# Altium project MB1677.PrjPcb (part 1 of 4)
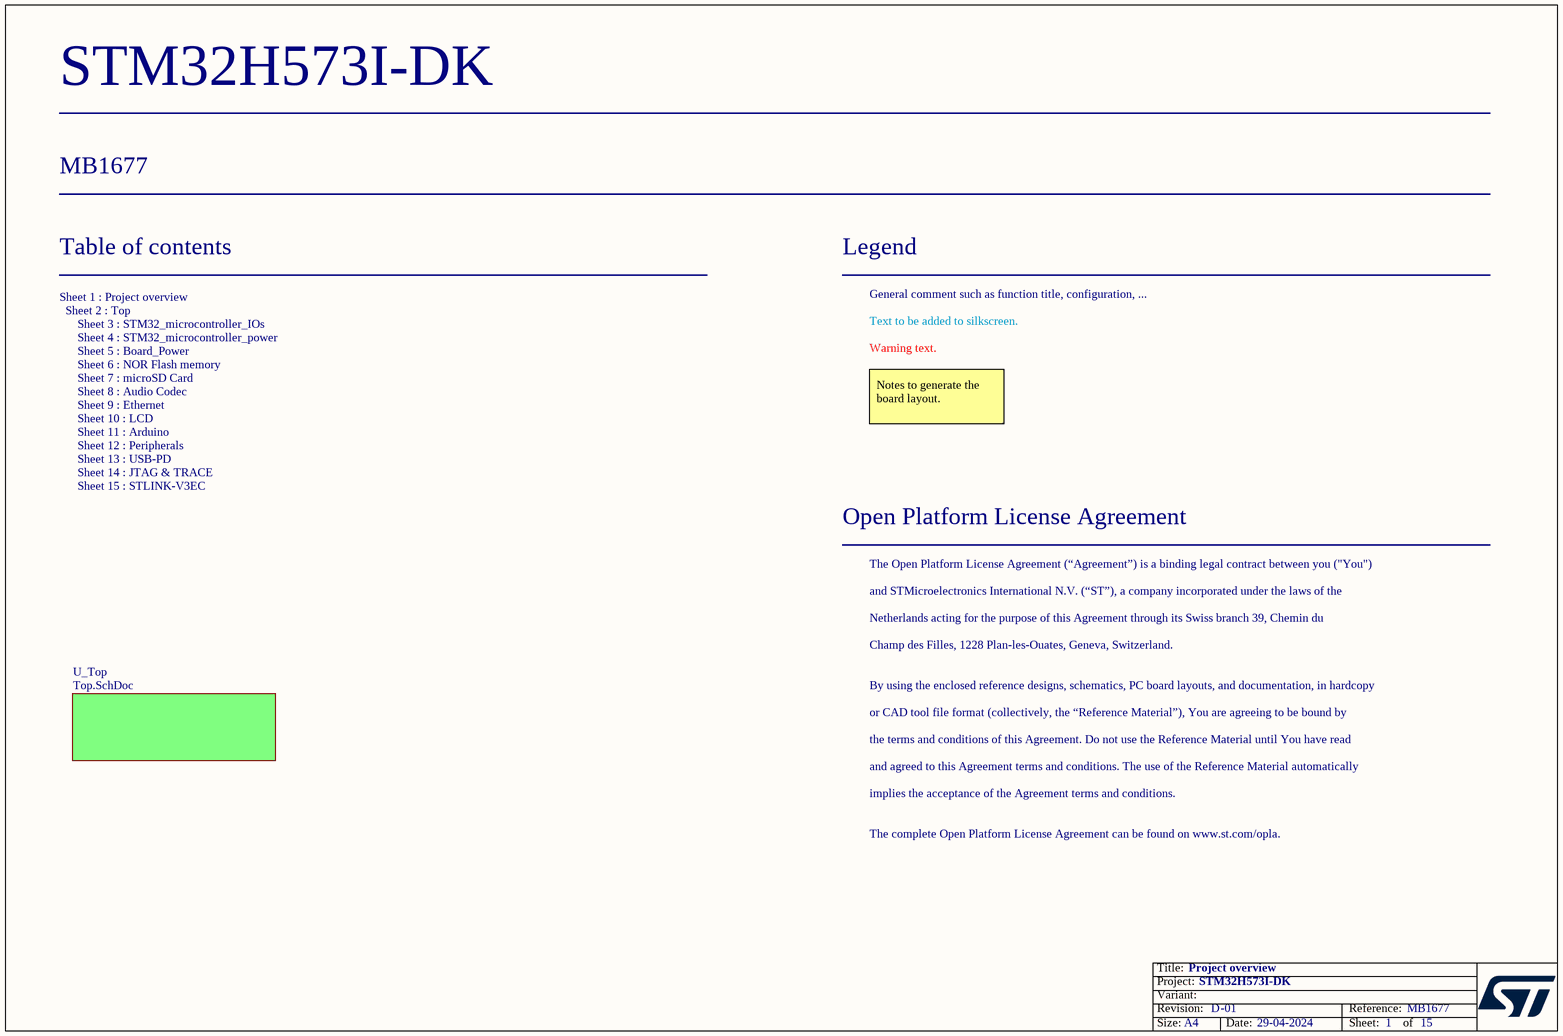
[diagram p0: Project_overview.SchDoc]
Board_Reference: MB1677; Board_PCB_Revision: D; Board_Name: STM32H573I-DK; Board_Document_Date: 29-04-2024; Board_Assembly_Revision: 01
15 sheets, 399 parts. Net scope: flat (ports and power ports of the same name join across sheets).
Board file: MB1677.PcbDoc
Sheets:
  Project_overview.SchDoc
    U_Top = Top.SchDoc
      U_Audio_Codec = Audio_Codec.SchDoc
      U_LCD = LCD.SchDoc
      U_Peripherals = Peripherals.SchDoc
      U_Arduino = Arduino.SchDoc
      U_JTAG = JTAG.SchDoc
      U_Ethernet = Ethernet.SchDoc
      U_STLINK_V3EC = STLINK_V3EC.SchDoc
      U_Board_power = Board_power.SchDoc
      U_STM32_microcontroller_power = STM32_microcontroller_power.SchDoc
      U_STM32_microcontroller_IOs = STM32_microcontroller_IOs.SchDoc
      U_USB-PD = USB-PD.SchDoc
      U_microSDcard = microSDcard.SchDoc
      U_NOR Flash memory = NOR_Flash_memory.SchDoc

## Sheet Project_overview.SchDoc: Project overview
size A4; Date: Not used; ApprovedBy: Not used; CheckedBy: Not used; Author: Not used; CompanyName: STMicroelectronics; DrawnBy: Not used; Engineer: Not used; Organization: Not used; Address1: Not used; Address2: Not used; Address3: Not used; Address4: Not used; DocumentNumber: 1; Revision: Not used; SheetNumber: 1; SheetTotal: 15

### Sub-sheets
U_Top = Top.SchDoc: no entries

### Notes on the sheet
- Table of contents
- Legend
- General comment such as function title, configuration, ...
- Text to be added to silkscreen.
- Warning text.
- Notes to generate the board layout.
- Sheet 1 : Project overview
  Sheet 2 : Top
  Sheet 3 : STM32_microcontroller_IOs
  Sheet 4 : STM32_microcontroller_power
  Sheet 5 : Board_Power
  Sheet 6 : NOR Flash memory
  Sheet 7 : microSD Card
  Sheet 8 : Audio Codec
  Sheet 9 : Ethernet
  Sheet 10 : LCD
  Sheet 11 : Arduino
  Sheet 12 : Peripherals
  Sheet 13 : USB-PD
  Sheet 14 : JTAG & TRACE
  Sheet 15 : STLINK-V3EC
- Open Platform License Agreement
- The Open Platform License Agreement (“Agreement”) is a binding legal contract between you ("You")
- and STMicroelectronics International N.V. (“ST”), a company incorporated under the laws of the
- Netherlands acting for the purpose of this Agreement through its Swiss branch 39, Chemin du
- Champ des Filles, 1228 Plan-les-Ouates, Geneva, Switzerland.
- By using the enclosed reference designs, schematics, PC board layouts, and documentation, in hardcopy
- or CAD tool file format (collectively, the “Reference Material”), You are agreeing to be bound by
- the terms and conditions of this Agreement. Do not use the Reference Material until You have read
- and agreed to this Agreement terms and conditions. The use of the Reference Material automatically
- implies the acceptance of the Agreement terms and conditions.
- The complete Open Platform License Agreement can be found on www.st.com/opla.

## Sheet Top.SchDoc: TOP
size A3; Date: Not used; ApprovedBy: Not used; CheckedBy: Not used; Author: Not used; CompanyName: STMicroelectronics; DrawnBy: Not used; Engineer: Not used; Organization: Not used; Address1: Not used; Address2: Not used; Address3: Not used; Address4: Not used; DocumentNumber: 2; Revision: Not used; SheetNumber: 2; SheetTotal: 15
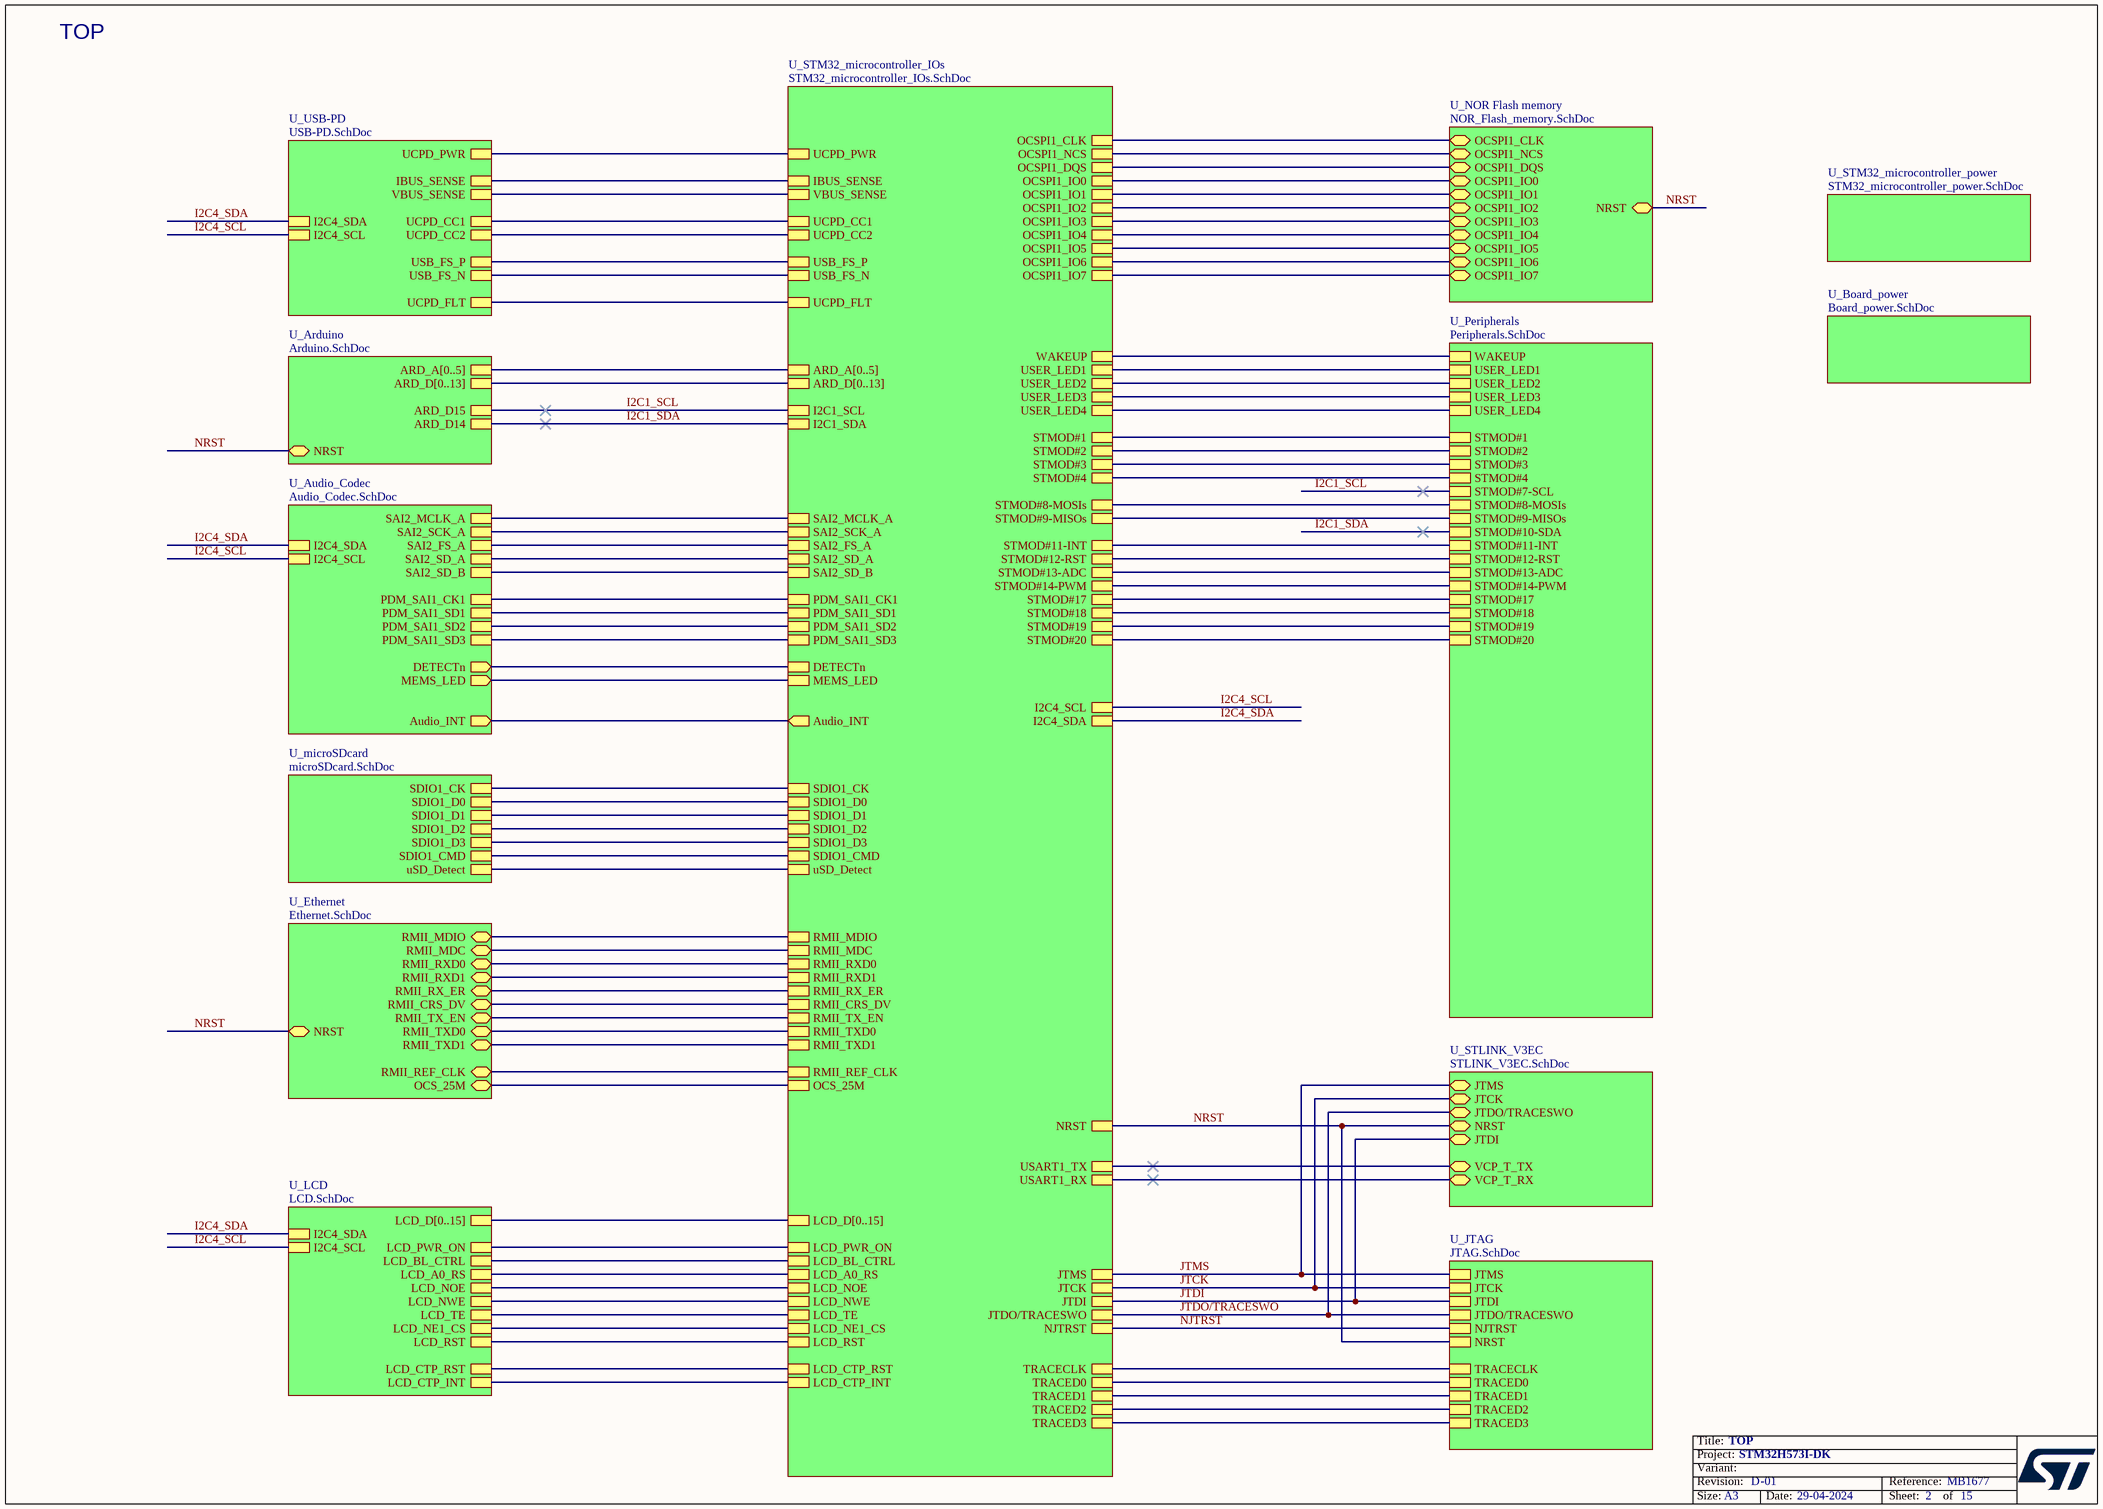
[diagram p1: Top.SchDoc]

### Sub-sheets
U_Arduino = Arduino.SchDoc: ARD_D15, ARD_D14, ARD_A[0..5], NRST (bidir), ARD_D[0..13]
U_Audio_Codec = Audio_Codec.SchDoc: Audio_INT (out), MEMS_LED (out), SAI2_SCK_A, SAI2_MCLK_A, SAI2_SD_B, DETECTn (out), SAI2_FS_A, SAI2_SD_A, I2C4_SCL, I2C4_SDA, PDM_SAI1_CK1, PDM_SAI1_SD2, PDM_SAI1_SD1, PDM_SAI1_SD3
U_Board_power = Board_power.SchDoc: no entries
U_Ethernet = Ethernet.SchDoc: RMII_TXD0 (bidir), RMII_TX_EN (bidir), RMII_RXD0 (bidir), RMII_REF_CLK (bidir), RMII_CRS_DV (bidir), RMII_MDC (bidir), RMII_MDIO (bidir), NRST (bidir), RMII_TXD1 (bidir), RMII_RXD1 (bidir), RMII_RX_ER (bidir), OCS_25M (bidir)
U_JTAG = JTAG.SchDoc: JTMS, JTCK, JTDI, JTDO/TRACESWO, NJTRST, NRST, TRACED0, TRACED1, TRACECLK, TRACED2, TRACED3
U_LCD = LCD.SchDoc: LCD_BL_CTRL, LCD_PWR_ON, LCD_RST, LCD_A0_RS, LCD_CTP_RST, LCD_TE, LCD_NOE, LCD_NE1_CS, LCD_D[0..15], LCD_CTP_INT, LCD_NWE, I2C4_SCL, I2C4_SDA
U_microSDcard = microSDcard.SchDoc: SDIO1_D0, SDIO1_D1, SDIO1_D2, SDIO1_D3, SDIO1_CMD, SDIO1_CK, uSD_Detect
U_NOR Flash memory = NOR_Flash_memory.SchDoc: NRST (bidir), OCSPI1_IO0 (bidir), OCSPI1_IO1 (bidir), OCSPI1_IO2 (bidir), OCSPI1_IO3 (bidir), OCSPI1_IO4 (bidir), OCSPI1_IO5 (bidir), OCSPI1_IO6 (bidir), OCSPI1_IO7 (bidir), OCSPI1_DQS (bidir), OCSPI1_CLK (bidir), OCSPI1_NCS (bidir)
U_Peripherals = Peripherals.SchDoc: WAKEUP, USER_LED2, USER_LED1, STMOD#2, STMOD#1, STMOD#4, USER_LED3, USER_LED4, STMOD#14-PWM, STMOD#8-MOSIs, STMOD#3, STMOD#13-ADC, STMOD#9-MISOs, STMOD#7-SCL, STMOD#10-SDA, STMOD#11-INT, STMOD#12-RST, STMOD#17, STMOD#18, STMOD#19, STMOD#20
U_STLINK_V3EC = STLINK_V3EC.SchDoc: JTCK (bidir), JTMS (bidir), JTDI (bidir), VCP_T_TX (bidir), VCP_T_RX (bidir), JTDO/TRACESWO (bidir), NRST (bidir)
U_STM32_microcontroller_IOs = STM32_microcontroller_IOs.SchDoc: OCSPI1_NCS, SAI2_MCLK_A, NRST, OCSPI1_DQS, OCSPI1_CLK, LCD_D[0..15], uSD_Detect, RMII_MDIO, SAI2_SD_B, SAI2_FS_A, SAI2_SCK_A, SAI2_SD_A, USER_LED2, JTMS, JTCK, JTDI, JTDO/TRACESWO, NJTRST, OCSPI1_IO1, OCSPI1_IO2, OCSPI1_IO3, OCSPI1_IO4, OCSPI1_IO7, OCSPI1_IO6, OCSPI1_IO5, RMII_CRS_DV, WAKEUP, USER_LED1, RMII_RXD1, UCPD_CC1, STMOD#1, STMOD#2, STMOD#4, STMOD#3, STMOD#9-MISOs, STMOD#8-MOSIs, STMOD#13-ADC, USART1_TX, USART1_RX, STMOD#11-INT, STMOD#12-RST, STMOD#14-PWM, STMOD#18, RMII_REF_CLK, RMII_RXD0, RMII_TXD0, ARD_A[0..5], ARD_D[0..13], RMII_MDC, RMII_TXD1, RMII_TX_EN, SDIO1_D0, SDIO1_D1, SDIO1_D2, SDIO1_D3, SDIO1_CK, SDIO1_CMD, OCSPI1_IO0, LCD_RST, LCD_BL_CTRL, LCD_CTP_RST, LCD_PWR_ON, USER_LED3, USER_LED4, UCPD_CC2, OCS_25M, LCD_CTP_INT, LCD_NE1_CS, LCD_NOE, LCD_NWE, USB_FS_N, USB_FS_P, RMII_RX_ER, LCD_A0_RS, I2C4_SCL, I2C4_SDA, IBUS_SENSE, UCPD_PWR, UCPD_FLT, VBUS_SENSE, DETECTn, MEMS_LED, LCD_TE, I2C1_SCL, I2C1_SDA, Audio_INT (out), PDM_SAI1_SD3, PDM_SAI1_CK1, PDM_SAI1_SD2, PDM_SAI1_SD1, STMOD#19, STMOD#20, STMOD#17, TRACECLK, TRACED0, TRACED1, TRACED2, TRACED3
U_STM32_microcontroller_power = STM32_microcontroller_power.SchDoc: no entries
U_USB-PD = USB-PD.SchDoc: UCPD_PWR, IBUS_SENSE, UCPD_CC1, UCPD_CC2, UCPD_FLT, USB_FS_P, USB_FS_N, VBUS_SENSE, I2C4_SCL, I2C4_SDA

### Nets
I2C1_SCL: sheet U_Peripherals/STMOD#7-SCL, sheet U_Arduino/ARD_D15, sheet U_STM32_microcontroller_IOs/I2C1_SCL
I2C1_SDA: sheet U_Peripherals/STMOD#10-SDA, sheet U_Arduino/ARD_D14, sheet U_STM32_microcontroller_IOs/I2C1_SDA
I2C4_SCL: sheet U_Audio_Codec/I2C4_SCL, sheet U_LCD/I2C4_SCL, sheet U_STM32_microcontroller_IOs/I2C4_SCL, sheet U_USB-PD/I2C4_SCL
I2C4_SDA: sheet U_Audio_Codec/I2C4_SDA, sheet U_LCD/I2C4_SDA, sheet U_STM32_microcontroller_IOs/I2C4_SDA, sheet U_USB-PD/I2C4_SDA
JTCK: sheet U_JTAG/JTCK, sheet U_STLINK_V3EC/JTCK, sheet U_STM32_microcontroller_IOs/JTCK
JTDI: sheet U_JTAG/JTDI, sheet U_STLINK_V3EC/JTDI, sheet U_STM32_microcontroller_IOs/JTDI
JTDO/TRACESWO: sheet U_JTAG/JTDO/TRACESWO, sheet U_STLINK_V3EC/JTDO/TRACESWO, sheet U_STM32_microcontroller_IOs/JTDO/TRACESWO
JTMS: sheet U_JTAG/JTMS, sheet U_STLINK_V3EC/JTMS, sheet U_STM32_microcontroller_IOs/JTMS
NJTRST: sheet U_JTAG/NJTRST, sheet U_STM32_microcontroller_IOs/NJTRST
NRST: sheet U_Arduino/NRST, sheet U_JTAG/NRST, sheet U_Ethernet/NRST, sheet U_STLINK_V3EC/NRST, sheet U_STM32_microcontroller_IOs/NRST, sheet U_NOR Flash memory/NRST
(unnamed): sheet U_Audio_Codec/Audio_INT, sheet U_STM32_microcontroller_IOs/Audio_INT
(unnamed): sheet U_Audio_Codec/MEMS_LED, sheet U_STM32_microcontroller_IOs/MEMS_LED  [a separate net that carries the same name]
(unnamed): sheet U_Audio_Codec/SAI2_SCK_A, sheet U_STM32_microcontroller_IOs/SAI2_SCK_A  [a separate net that carries the same name]
(unnamed): sheet U_Audio_Codec/SAI2_MCLK_A, sheet U_STM32_microcontroller_IOs/SAI2_MCLK_A  [a separate net that carries the same name]
(unnamed): sheet U_Audio_Codec/SAI2_SD_B, sheet U_STM32_microcontroller_IOs/SAI2_SD_B  [a separate net that carries the same name]
(unnamed): sheet U_Audio_Codec/DETECTn, sheet U_STM32_microcontroller_IOs/DETECTn  [a separate net that carries the same name]
(unnamed): sheet U_Audio_Codec/SAI2_FS_A, sheet U_STM32_microcontroller_IOs/SAI2_FS_A  [a separate net that carries the same name]
(unnamed): sheet U_Audio_Codec/SAI2_SD_A, sheet U_STM32_microcontroller_IOs/SAI2_SD_A  [a separate net that carries the same name]
(unnamed): sheet U_Audio_Codec/PDM_SAI1_CK1, sheet U_STM32_microcontroller_IOs/PDM_SAI1_CK1  [a separate net that carries the same name]
(unnamed): sheet U_Audio_Codec/PDM_SAI1_SD2, sheet U_STM32_microcontroller_IOs/PDM_SAI1_SD2  [a separate net that carries the same name]
(unnamed): sheet U_Audio_Codec/PDM_SAI1_SD1, sheet U_STM32_microcontroller_IOs/PDM_SAI1_SD1  [a separate net that carries the same name]
(unnamed): sheet U_Audio_Codec/PDM_SAI1_SD3, sheet U_STM32_microcontroller_IOs/PDM_SAI1_SD3  [a separate net that carries the same name]
(unnamed): sheet U_LCD/LCD_BL_CTRL, sheet U_STM32_microcontroller_IOs/LCD_BL_CTRL  [a separate net that carries the same name]
(unnamed): sheet U_LCD/LCD_PWR_ON, sheet U_STM32_microcontroller_IOs/LCD_PWR_ON  [a separate net that carries the same name]
(unnamed): sheet U_LCD/LCD_RST, sheet U_STM32_microcontroller_IOs/LCD_RST  [a separate net that carries the same name]
(unnamed): sheet U_LCD/LCD_A0_RS, sheet U_STM32_microcontroller_IOs/LCD_A0_RS  [a separate net that carries the same name]
(unnamed): sheet U_LCD/LCD_CTP_RST, sheet U_STM32_microcontroller_IOs/LCD_CTP_RST  [a separate net that carries the same name]
(unnamed): sheet U_LCD/LCD_TE, sheet U_STM32_microcontroller_IOs/LCD_TE  [a separate net that carries the same name]
(unnamed): sheet U_LCD/LCD_NOE, sheet U_STM32_microcontroller_IOs/LCD_NOE  [a separate net that carries the same name]
(unnamed): sheet U_LCD/LCD_NE1_CS, sheet U_STM32_microcontroller_IOs/LCD_NE1_CS  [a separate net that carries the same name]
(unnamed): sheet U_LCD/LCD_CTP_INT, sheet U_STM32_microcontroller_IOs/LCD_CTP_INT  [a separate net that carries the same name]
(unnamed): sheet U_LCD/LCD_NWE, sheet U_STM32_microcontroller_IOs/LCD_NWE  [a separate net that carries the same name]
(unnamed): sheet U_Peripherals/WAKEUP, sheet U_STM32_microcontroller_IOs/WAKEUP  [a separate net that carries the same name]
(unnamed): sheet U_Peripherals/USER_LED2, sheet U_STM32_microcontroller_IOs/USER_LED2  [a separate net that carries the same name]
(unnamed): sheet U_Peripherals/USER_LED1, sheet U_STM32_microcontroller_IOs/USER_LED1  [a separate net that carries the same name]
(unnamed): sheet U_Peripherals/STMOD#2, sheet U_STM32_microcontroller_IOs/STMOD#2  [a separate net that carries the same name]
(unnamed): sheet U_Peripherals/STMOD#1, sheet U_STM32_microcontroller_IOs/STMOD#1  [a separate net that carries the same name]
(unnamed): sheet U_Peripherals/STMOD#4, sheet U_STM32_microcontroller_IOs/STMOD#4  [a separate net that carries the same name]
(unnamed): sheet U_Peripherals/USER_LED3, sheet U_STM32_microcontroller_IOs/USER_LED3  [a separate net that carries the same name]
(unnamed): sheet U_Peripherals/USER_LED4, sheet U_STM32_microcontroller_IOs/USER_LED4  [a separate net that carries the same name]
(unnamed): sheet U_Peripherals/STMOD#14-PWM, sheet U_STM32_microcontroller_IOs/STMOD#14-PWM  [a separate net that carries the same name]
(unnamed): sheet U_Peripherals/STMOD#8-MOSIs, sheet U_STM32_microcontroller_IOs/STMOD#8-MOSIs  [a separate net that carries the same name]
(unnamed): sheet U_Peripherals/STMOD#3, sheet U_STM32_microcontroller_IOs/STMOD#3  [a separate net that carries the same name]
(unnamed): sheet U_Peripherals/STMOD#13-ADC, sheet U_STM32_microcontroller_IOs/STMOD#13-ADC  [a separate net that carries the same name]
(unnamed): sheet U_Peripherals/STMOD#9-MISOs, sheet U_STM32_microcontroller_IOs/STMOD#9-MISOs  [a separate net that carries the same name]
(unnamed): sheet U_Peripherals/STMOD#11-INT, sheet U_STM32_microcontroller_IOs/STMOD#11-INT  [a separate net that carries the same name]
(unnamed): sheet U_Peripherals/STMOD#12-RST, sheet U_STM32_microcontroller_IOs/STMOD#12-RST  [a separate net that carries the same name]
(unnamed): sheet U_Peripherals/STMOD#17, sheet U_STM32_microcontroller_IOs/STMOD#17  [a separate net that carries the same name]
(unnamed): sheet U_Peripherals/STMOD#18, sheet U_STM32_microcontroller_IOs/STMOD#18  [a separate net that carries the same name]
(unnamed): sheet U_Peripherals/STMOD#19, sheet U_STM32_microcontroller_IOs/STMOD#19  [a separate net that carries the same name]
(unnamed): sheet U_Peripherals/STMOD#20, sheet U_STM32_microcontroller_IOs/STMOD#20  [a separate net that carries the same name]
(unnamed): sheet U_JTAG/TRACED0, sheet U_STM32_microcontroller_IOs/TRACED0  [a separate net that carries the same name]
(unnamed): sheet U_JTAG/TRACED1, sheet U_STM32_microcontroller_IOs/TRACED1  [a separate net that carries the same name]
(unnamed): sheet U_JTAG/TRACECLK, sheet U_STM32_microcontroller_IOs/TRACECLK  [a separate net that carries the same name]
(unnamed): sheet U_JTAG/TRACED2, sheet U_STM32_microcontroller_IOs/TRACED2  [a separate net that carries the same name]
(unnamed): sheet U_JTAG/TRACED3, sheet U_STM32_microcontroller_IOs/TRACED3  [a separate net that carries the same name]
(unnamed): sheet U_Ethernet/RMII_TXD0, sheet U_STM32_microcontroller_IOs/RMII_TXD0  [a separate net that carries the same name]
(unnamed): sheet U_Ethernet/RMII_TX_EN, sheet U_STM32_microcontroller_IOs/RMII_TX_EN  [a separate net that carries the same name]
(unnamed): sheet U_Ethernet/RMII_RXD0, sheet U_STM32_microcontroller_IOs/RMII_RXD0  [a separate net that carries the same name]
(unnamed): sheet U_Ethernet/RMII_REF_CLK, sheet U_STM32_microcontroller_IOs/RMII_REF_CLK  [a separate net that carries the same name]
(unnamed): sheet U_Ethernet/RMII_CRS_DV, sheet U_STM32_microcontroller_IOs/RMII_CRS_DV  [a separate net that carries the same name]
(unnamed): sheet U_Ethernet/RMII_MDC, sheet U_STM32_microcontroller_IOs/RMII_MDC  [a separate net that carries the same name]
(unnamed): sheet U_Ethernet/RMII_MDIO, sheet U_STM32_microcontroller_IOs/RMII_MDIO  [a separate net that carries the same name]
(unnamed): sheet U_Ethernet/RMII_TXD1, sheet U_STM32_microcontroller_IOs/RMII_TXD1  [a separate net that carries the same name]
(unnamed): sheet U_Ethernet/RMII_RXD1, sheet U_STM32_microcontroller_IOs/RMII_RXD1  [a separate net that carries the same name]
(unnamed): sheet U_Ethernet/RMII_RX_ER, sheet U_STM32_microcontroller_IOs/RMII_RX_ER  [a separate net that carries the same name]
(unnamed): sheet U_Ethernet/OCS_25M, sheet U_STM32_microcontroller_IOs/OCS_25M  [a separate net that carries the same name]
(unnamed): sheet U_STLINK_V3EC/VCP_T_TX, sheet U_STM32_microcontroller_IOs/USART1_TX  [a separate net that carries the same name]
(unnamed): sheet U_STLINK_V3EC/VCP_T_RX, sheet U_STM32_microcontroller_IOs/USART1_RX  [a separate net that carries the same name]
(unnamed): sheet U_STM32_microcontroller_IOs/OCSPI1_NCS, sheet U_NOR Flash memory/OCSPI1_NCS  [a separate net that carries the same name]
(unnamed): sheet U_STM32_microcontroller_IOs/OCSPI1_DQS, sheet U_NOR Flash memory/OCSPI1_DQS  [a separate net that carries the same name]
(unnamed): sheet U_STM32_microcontroller_IOs/OCSPI1_CLK, sheet U_NOR Flash memory/OCSPI1_CLK  [a separate net that carries the same name]
(unnamed): sheet U_STM32_microcontroller_IOs/uSD_Detect, sheet U_microSDcard/uSD_Detect  [a separate net that carries the same name]
(unnamed): sheet U_STM32_microcontroller_IOs/OCSPI1_IO1, sheet U_NOR Flash memory/OCSPI1_IO1  [a separate net that carries the same name]
(unnamed): sheet U_STM32_microcontroller_IOs/OCSPI1_IO2, sheet U_NOR Flash memory/OCSPI1_IO2  [a separate net that carries the same name]
(unnamed): sheet U_STM32_microcontroller_IOs/OCSPI1_IO3, sheet U_NOR Flash memory/OCSPI1_IO3  [a separate net that carries the same name]
(unnamed): sheet U_STM32_microcontroller_IOs/OCSPI1_IO4, sheet U_NOR Flash memory/OCSPI1_IO4  [a separate net that carries the same name]
(unnamed): sheet U_STM32_microcontroller_IOs/OCSPI1_IO7, sheet U_NOR Flash memory/OCSPI1_IO7  [a separate net that carries the same name]
(unnamed): sheet U_STM32_microcontroller_IOs/OCSPI1_IO6, sheet U_NOR Flash memory/OCSPI1_IO6  [a separate net that carries the same name]
(unnamed): sheet U_STM32_microcontroller_IOs/OCSPI1_IO5, sheet U_NOR Flash memory/OCSPI1_IO5  [a separate net that carries the same name]
(unnamed): sheet U_STM32_microcontroller_IOs/UCPD_CC1, sheet U_USB-PD/UCPD_CC1  [a separate net that carries the same name]
(unnamed): sheet U_STM32_microcontroller_IOs/SDIO1_D0, sheet U_microSDcard/SDIO1_D0  [a separate net that carries the same name]
(unnamed): sheet U_STM32_microcontroller_IOs/SDIO1_D1, sheet U_microSDcard/SDIO1_D1  [a separate net that carries the same name]
(unnamed): sheet U_STM32_microcontroller_IOs/SDIO1_D2, sheet U_microSDcard/SDIO1_D2  [a separate net that carries the same name]
(unnamed): sheet U_STM32_microcontroller_IOs/SDIO1_D3, sheet U_microSDcard/SDIO1_D3  [a separate net that carries the same name]
(unnamed): sheet U_STM32_microcontroller_IOs/SDIO1_CK, sheet U_microSDcard/SDIO1_CK  [a separate net that carries the same name]
(unnamed): sheet U_STM32_microcontroller_IOs/SDIO1_CMD, sheet U_microSDcard/SDIO1_CMD  [a separate net that carries the same name]
(unnamed): sheet U_STM32_microcontroller_IOs/OCSPI1_IO0, sheet U_NOR Flash memory/OCSPI1_IO0  [a separate net that carries the same name]
(unnamed): sheet U_STM32_microcontroller_IOs/UCPD_CC2, sheet U_USB-PD/UCPD_CC2  [a separate net that carries the same name]
(unnamed): sheet U_STM32_microcontroller_IOs/USB_FS_N, sheet U_USB-PD/USB_FS_N  [a separate net that carries the same name]
(unnamed): sheet U_STM32_microcontroller_IOs/USB_FS_P, sheet U_USB-PD/USB_FS_P  [a separate net that carries the same name]
(unnamed): sheet U_STM32_microcontroller_IOs/IBUS_SENSE, sheet U_USB-PD/IBUS_SENSE  [a separate net that carries the same name]
(unnamed): sheet U_STM32_microcontroller_IOs/UCPD_PWR, sheet U_USB-PD/UCPD_PWR  [a separate net that carries the same name]
(unnamed): sheet U_STM32_microcontroller_IOs/UCPD_FLT, sheet U_USB-PD/UCPD_FLT  [a separate net that carries the same name]
(unnamed): sheet U_STM32_microcontroller_IOs/VBUS_SENSE, sheet U_USB-PD/VBUS_SENSE  [a separate net that carries the same name]

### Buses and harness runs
bus sheet U_Arduino/ARD_A[0..5] = sheet U_STM32_microcontroller_IOs/ARD_A[0..5]
bus sheet U_Arduino/ARD_D[0..13] = sheet U_STM32_microcontroller_IOs/ARD_D[0..13]
bus sheet U_LCD/LCD_D[0..15] = sheet U_STM32_microcontroller_IOs/LCD_D[0..15]

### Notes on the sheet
- TOP

## Sheet Audio_Codec.SchDoc: Audio Codec
size A4; Date: Not used; ApprovedBy: Not used; CheckedBy: Not used; Author: Not used; CompanyName: STMicroelectronics; DrawnBy: Not used; Engineer: Not used; Organization: Not used; Address1: Not used; Address2: Not used; Address3: Not used; Address4: Not used; DocumentNumber: 8; Revision: Not used; SheetNumber: 8; SheetTotal: 15
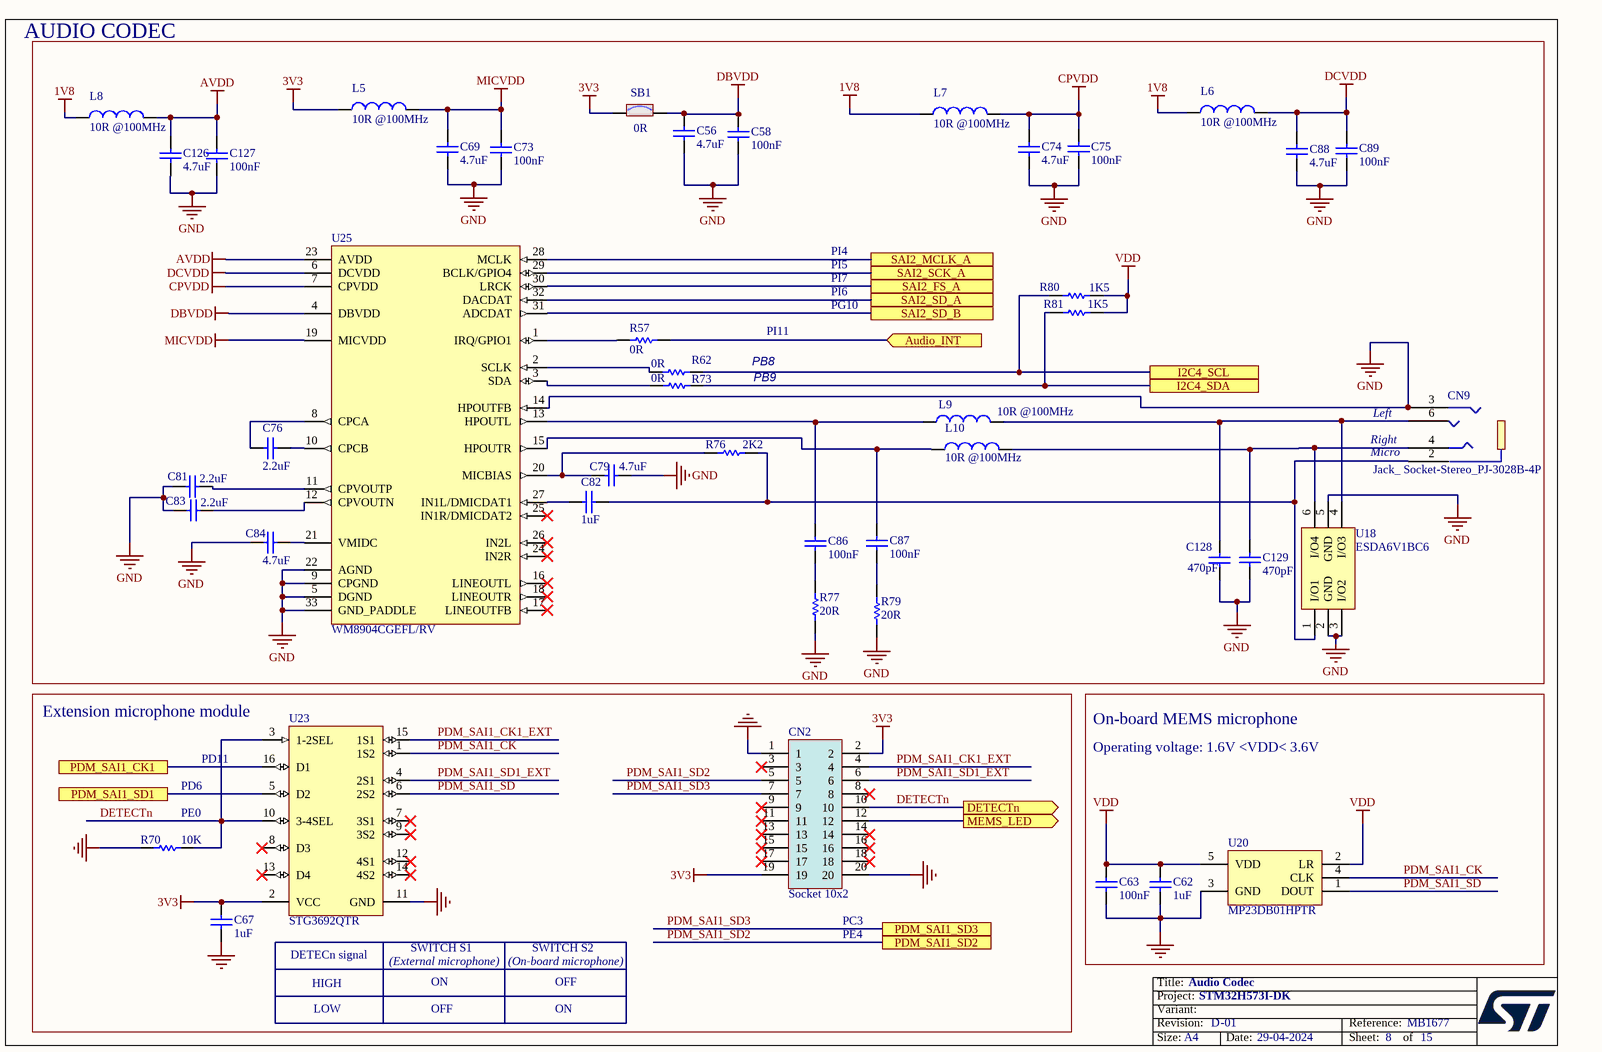
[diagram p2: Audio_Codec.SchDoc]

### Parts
C56  value 4.7uF  [C0603]  (hidden comment: Capacitor)
C58  value 100nF  [C0402]  (hidden comment: Capacitor)
C62  value 1uF  [C0402]  (hidden comment: Capacitor)
C63  value 100nF  [C0402]  (hidden comment: Capacitor)
C67  value 1uF  [C0402]  (hidden comment: Capacitor)
C69  value 4.7uF  [C0603]  (hidden comment: Capacitor)
C73  value 100nF  [C0402]  (hidden comment: Capacitor)
C74  value 4.7uF  [C0603]  (hidden comment: Capacitor)
C75  value 100nF  [C0402]  (hidden comment: MCD-00006)
C76  value 2.2uF  [C0603]  (hidden comment: Capacitor)
C79  value 4.7uF  [C0603]  (hidden comment: Capacitor)
C81  value 2.2uF  [C0603]  (hidden comment: Capacitor)
C82  value 1uF  [C0603]  (hidden comment: Capacitor)
C83  value 2.2uF  [C0603]  (hidden comment: Capacitor)
C84  value 4.7uF  [C0603]  (hidden comment: Capacitor)
C86  value 100nF  [C0402]  (hidden comment: Capacitor)
C87  value 100nF  [C0402]  (hidden comment: Capacitor)
C88  value 4.7uF  [C0603]  (hidden comment: Capacitor)
C89  value 100nF  [C0402]  (hidden comment: Capacitor)
C126  value 4.7uF  [C0603]  (hidden comment: Capacitor)
C127  value 100nF  [C0402]  (hidden comment: Capacitor)
C128  value 470pF  [C0402]  (hidden comment: Capacitor)
C129  value 470pF  [C0402]  (hidden comment: Capacitor)
CN2  Socket 10x2  [CON_FCI_20021311-XXX20XXLF]
CN9  value Jack_ Socket-Stereo_PJ-3028B-4P  [CON_PHONE-JACK-3P5_HY_PJ3028B]  (hidden comment: Jack_PJ3028B-3_4P)
L5  value 10R @100MHz  [IND_0402_MURATA_BLM15H_H0P5]  (hidden comment: Inductor)
L6  value 10R @100MHz  [IND_0402_MURATA_BLM15H_H0P5]  (hidden comment: Inductor)
L7  value 10R @100MHz  [IND_0402_MURATA_BLM15H_H0P5]  (hidden comment: Inductor)
L8  value 10R @100MHz  [IND_0402_MURATA_BLM15H_H0P5]  (hidden comment: Inductor)
L9  value 10R @100MHz  [IND_0402_MURATA_BLM15H_H0P5]  (hidden comment: Inductor)
L10  value 10R @100MHz  [IND_0402_MURATA_BLM15H_H0P5]  (hidden comment: Inductor)
R57  value 0R  [R0603]  (hidden comment: Resistor)
R62  value 0R  [R0603]  (hidden comment: Resistor)
R70  value 10K  [R0402]  (hidden comment: Resistor)
R73  value 0R  [R0603]  (hidden comment: Resistor)
R76  value 2K2  [R0402]  (hidden comment: Resistor)
R77  value 20R  [R0603]  (hidden comment: Resistor)
R79  value 20R  [R0603]  (hidden comment: Resistor)
R80  value 1K5  [R0402]  (hidden comment: Resistor)
R81  value 1K5  [R0402]  (hidden comment: Resistor)
SB1  value 0R  [SOLDER-BRIDGE_R0603-0R]  (hidden comment: SB_ON)
U18  ESDA6V1BC6  [ESD_SOT23-6L]
U20  value MP23DB01HPTR  [MIC_STM_MP23DB01MMTR]  (hidden comment: MP23DB01MMTR)
U23  STG3692QTR  [ICC_UFQFN16-EPAD_2P6X1P8_P040]
U25  WM8904CGEFL/RV  [ICC_QFN32-EPAD_4X4_P040]

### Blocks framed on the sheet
Extension microphone module: C67 CN2 R70 U23
On-board MEMS microphone: C62 C63 U20

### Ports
Audio_INT (in), DETECTn (out), I2C4_SCL, I2C4_SDA, MEMS_LED (out), PDM_SAI1_CK1, PDM_SAI1_SD1, PDM_SAI1_SD2, PDM_SAI1_SD3, SAI2_FS_A, SAI2_MCLK_A, SAI2_SCK_A, SAI2_SD_A, SAI2_SD_B

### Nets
1V8: L6.1 L7.1 L8.1
3V3: C67.2 CN2.2 CN2.19 L5.1 SB1.1 U23.2(VCC)
AVDD: C126.2 C127.2 L8.2 U25.23(AVDD)
CPVDD: C74.2 C75.2 L7.2 U25.7(CPVDD)
DBVDD: C56.2 C58.2 SB1.2 U25.4(DBVDD)
DCVDD: C88.2 C89.2 L6.2 U25.6(DCVDD)
GND: C56.1 C58.1 C62.2 C63.1 C67.1 C69.1 C73.1 C74.1 C75.1 C79.2 C81.1 C83.1 C84.1 C88.1 C89.1 C126.1 C127.1 C128.1 C129.1 CN2.1 CN2.20 CN9.3 R70.1 R77.1 R79.1 U18.2(GND) U18.3(I/O2) U18.5(GND) U20.3(GND) U23.11(GND) U25.5(DGND) U25.9(CPGND) U25.14(HPOUTFB) U25.22(AGND) U25.33(GND_PADDLE)
MICVDD: C69.2 C73.2 L5.2 U25.19(MICVDD)
VDD: C62.1 C63.2 R80.2 R81.2 U20.2(LR) U20.5(VDD)
Audio_INT: R57.1 ; port Audio_INT
DETECTn: CN2.10 R70.2 U23.3(1-2SEL) U23.10(3-4SEL) ; port DETECTn
I2C4_SCL: R62.2 R80.1 ; port I2C4_SCL
I2C4_SDA: R73.2 R81.1 ; port I2C4_SDA
MEMS_LED: CN2.12 ; port MEMS_LED
PDM_SAI1_CK: U20.4(CLK) U23.1(1S2)
PDM_SAI1_CK1: U23.16(D1) ; port PDM_SAI1_CK1
PDM_SAI1_CK1_EXT: CN2.4 U23.15(1S1)
PDM_SAI1_SD: U20.1(DOUT) U23.6(2S2)
PDM_SAI1_SD1: U23.5(D2) ; port PDM_SAI1_SD1
PDM_SAI1_SD1_EXT: CN2.6 U23.4(2S1)
PDM_SAI1_SD2: CN2.5 ; port PDM_SAI1_SD2
PDM_SAI1_SD3: CN2.7 ; port PDM_SAI1_SD3
SAI2_FS_A: U25.30(LRCK) ; port SAI2_FS_A
SAI2_MCLK_A: U25.28(MCLK) ; port SAI2_MCLK_A
SAI2_SCK_A: U25.29(BCLK/GPIO4) ; port SAI2_SCK_A
SAI2_SD_A: U25.32(DACDAT) ; port SAI2_SD_A
SAI2_SD_B: U25.31(ADCDAT) ; port SAI2_SD_B
NetC76_1: C76.1 U25.8(CPCA)
NetC76_2: C76.2 U25.10(CPCB)
NetC79_1: C79.1 R76.1 U25.20(MICBIAS)
NetC81_2: C81.2 U25.11(CPVOUTP)
NetC82_1: C82.1 U25.27(IN1L/DMICDAT1)
NetC82_2: C82.2 CN9.2 R76.2 U18.1(I/O1)
NetC83_2: C83.2 U25.12(CPVOUTN)
NetC84_2: C84.2 U25.21(VMIDC)
NetC86_1: C86.1 R77.2
NetC86_2: C86.2 L9.1 U25.13(HPOUTL)
NetC87_1: C87.1 R79.2
NetC87_2: C87.2 L10.1 U25.15(HPOUTR)
NetC128_2: C128.2 CN9.6 L9.2 U18.4(I/O3)
NetC129_2: C129.2 CN9.4 L10.2 U18.6(I/O4)
NetR57_2: R57.2 U25.1(IRQ/GPIO1)
NetR62_1: R62.1 U25.2(SCLK)
NetR73_1: R73.1 U25.3(SDA)

Not connected (* = marked no-connect by the designer): CN2 3* 8* 9* 11* 13* 14* 15* 16* 17* 18*; U23 7(3S1)* 8(D3)* 9(3S2)* 12(4S1)* 13(D4)* 14(4S2)*; U25 16(LINEOUTL)* 17(LINEOUTFB)* 18(LINEOUTR)* 24(IN2R)* 25(IN1R/DMICDAT2)* 26(IN2L)*

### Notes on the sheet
- AUDIO CODEC
- PI4
- PI5
- PI7
- PI6
- PG10
- PB8
- PB9
- PI11
- (near CN9) Right
- Micro
- (near CN9) Left
- PD6
- PD11
- Operating voltage: 1.6V <VDD< 3.6V
- (near R70) PE0
- PE4
- (near CN2) PC3
- DETECn signal
- HIGH
- (External microphone)
- (near U23) SWITCH S1
- ON
- (On-board microphone)
- SWITCH S2
- OFF
- LOW

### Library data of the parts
C56 C69 C74 C79 C84 C88 C126 = MCD-00009: Capacitor, MLCC, 4.7uF, 16V, X5R, +/-10%, 0603, T=0.8mm; Part_Preference: Recommended; Manufacturer: YAGEO; Manufacturer_Part_Number: CC0603KRX5R7BB475; Partial_Alternate_Internal_Part_Number: MCD-03565; Component_Country_Of_Origin: China; Alternate_EMS: A; ShowFields: YES; ID: 2471
C58 C73 C75 C86 C87 C89 C127 = MCD-00006: Capacitor, MLCC, 100nF, 16V, X7R, +/-10%, 0402, T=0.5mm; Part_Preference: Recommended; Manufacturer: YAGEO; Manufacturer_Part_Number: CC0402KRX7R7BB104; Partial_Alternate_Internal_Part_Number: MCD-03299; Order_Code_RS: 9402047; Component_Country_Of_Origin: China; ShowFields: YES; ID: 2474
C62 = MCD-01722: Capacitor, 1uF, 10V, X5R, 10%, 0402, T=0.5mm; Manufacturer_Part_Number: CC0402KRX5R6BB105; Manufacturer: YAGEO; Part_Preference: Recommended; Provided_By: SUBCO; Component_Country_Of_Origin: China; ID: 3822; ShowFields: YES
C63 = MCD-00006: Capacitor, MLCC, 100nF, 16V, X7R, +/-10%, 0402, T=0.5mm; Part_Preference: Recommended; Manufacturer: YAGEO; Manufacturer_Part_Number: CC0402KRX7R7BB104; Partial_Alternate_Internal_Part_Number: MCD-03299; Order_Code_RS: 9402047; Component_Country_Of_Origin: China; ID: 2474; ShowFields: YES
C67 = MCD-00095: Capacitor, MLCC, 1uF, 25V, X5R, +/-10%, 0402, T=0.5mm; Part_Preference: Recommended; Manufacturer: MURATA; Manufacturer_Part_Number: GRM155R61E105KA12; Order_Code_RS: 2218855; Component_Country_Of_Origin: Japan°°; ID: 2772; ShowFields: YES
C76 C81 C83 = MCD-00012: Capacitor, MLCC, 2.2uF, 10V, X5R, +/- 10%, 0603, T=0.8mm; BMS_Part_Number: 9142010; Part_Preference: Recommended; Manufacturer: YAGEO; Manufacturer_Part_Number: CC0603KRX5R6BB225; Partial_Alternate_Internal_Part_Number: MCD-00551; Order_Code_RS: 2370679; Component_Country_Of_Origin: China; ShowFields: YES; ID: 2467
C82 = MCD-00010: Capacitor, MLCC, 1uF, 16V, X5R, +/-10%, 0603, T=0.8mm; Part_Preference: Recommended; Manufacturer: YAGEO; Manufacturer_Part_Number: CC0603KRX5R7BB105; Order_Code_RS: 2370680; Component_Country_Of_Origin: China; ShowFields: YES; ID: 2470
C128 C129 = MCD-00724: Capacitor, MLCC, 470pF, 50V, NPO, +/-5%, 0402, T=0.5mm; Part_Preference: Recommended; Manufacturer: YAGEO; Manufacturer_Part_Number: CC0402JRNPO9BN471; Order_Code_RS: 199-2186; Component_Country_Of_Origin: China; ShowFields: YES; ID: 3023
CN2 = MCD-00147: Socket for MB1299, 10x2, 1.27mm, VR, TH, Height 4.30mm/2.40mm; Part_Preference: Recommended; Part_Type: Connector; Manufacturer: AMPHENOL ICC; Manufacturer_Part_Number: 20021311-00020T4LF; Alternate_Manufacturer: JIUBABA; Alternate_Manufacturer_Part_Number: 234220S1410; Partial_Alternate_Internal_Part_Number: MCD-03007; Component_Country_Of_Origin: China; ID: 2719; Order_Code_RS: 170-8859; ShowFields: YES
CN9 = MCD-00263: Connector Jack Socket Stereo 3.5mm, 4 pins, RA, SMT, Black; Part_Preference: Recommended; Manufacturer: QIAOD; Manufacturer_Part_Number: PJ-3028B-4P; Component_Country_Of_Origin: Unknown; ID: 2608; ShowFields: YES
L5-L10 = MCD-02381: Ferrite bead, 10R @100MHz, 5R, 0.75A, 0.07R, 0402, T=0.22mm; Part_Preference: Recommended; Manufacturer: MURATA; Manufacturer_Part_Number: BLM02AX100SN1D; Component_Country_Of_Origin: Japan°°; ShowFields: YES; ID: 4487
R57 R62 R73 = MCD-00056: Resistor, 0R, 0603, +/-5%, 1/10W; Part_Preference: Recommended; Manufacturer: YAGEO; Manufacturer_Part_Number: RC0603JR-070RL; Order_Code_RS: 9233130RL; Component_Country_Of_Origin: China; ShowFields: YES; ID: 2536
R70 = MCD-00053: Resistor,10K,0402,1%,1/16W; BMS_Part_Number: 9131590; Part_Preference: Recommended; Manufacturer: YAGEO; Manufacturer_Part_Number: RC0402FR-0710KL; Order_Code_RS: 9239359; Component_Country_Of_Origin: China; ID: 2539; ShowFields: YES
R76 = MCD-00057: Resistor, 2K2, 0402, +/-1%, 1/16W; Part_Preference: Recommended; Manufacturer: YAGEO; Manufacturer_Part_Number: RC0402FR-072K2L; Order_Code_RS: 9239278; Component_Country_Of_Origin: China; ShowFields: YES; ID: 2534
R77 R79 = MCD-00345: Resistor, 20R, 0603, +/-1%, 1/10W; Part_Preference: Recommended; Manufacturer: YAGEO; Manufacturer_Part_Number: RC0603FR-0720RL; Component_Country_Of_Origin: China; ShowFields: YES; ID: 2933
R80 R81 = MCD-00068: Resistor, 1K5, 0402, +/-1%, 1/16W; Manufacturer_Part_Number: RC0402FR-071K5L; Manufacturer: YAGEO; Part_Preference: Recommended; Order_Code_RS: 9239251; Component_Country_Of_Origin: China; ShowFields: YES; ID: 2524
SB1 = MCD-00071: Resistor, 0R, SB0603, 5%, 0.1W; Manufacturer_Part_Number: RC0603JR-070RL; Manufacturer: YAGEO; Manufacturer_HQ_COO: Unknown; Part_Preference: Recommended; Component_Country_Of_Origin: China; ID: 2521; Order_Code_RS: 199-5647; ShowFields: YES
U18 = MCD-00247: Quad Bidir ESD protection; BMS_Part_Number: 9179038; Part_Preference: Recommended; Part_Type: Diode; Manufacturer: STMICROELECTRONICS; Manufacturer_HQ_COO: EU; Component_Country_Of_Origin: China; ID: 2624; Order_Code_RS: 248-805; ShowFields: YES
U20 = MCD-02122: MEMS sensors , omnidirectionnal digital microphone; Part_Type: IC; Part_Preference: Recommended; Manufacturer: STMICROELECTRONICS; Manufacturer_HQ_COO: EU; Component_Country_Of_Origin: China; ShowFields: YES; ID: 4222
U23 = MCD-00317: Low voltage high bandwidth quad SPDT switch; BMS_Part_Number: 9159018; Part_Preference: Recommended; Part_Type: IC; Manufacturer: STMICROELECTRONICS; Manufacturer_HQ_COO: EU; Component_Country_Of_Origin: Thailand; ID: 2961; ShowFields: YES
U25 = MCD-03825: Audio Codec, Ultra Low-Power Codec for Portable Audio Applications; Part_Type: IC; Part_Preference: Recommended; Manufacturer: CIRRUS LOGIC; Component_Country_Of_Origin: Taiwan; ShowFields: YES; ID: 5941

## Sheet LCD.SchDoc: LCD
size A4; Date: Not used; ApprovedBy: Not used; CheckedBy: Not used; Author: Not used; CompanyName: STMicroelectronics; DrawnBy: Not used; Engineer: Not used; Organization: Not used; Address1: Not used; Address2: Not used; Address3: Not used; Address4: Not used; DocumentNumber: 10; Revision: Not used; SheetNumber: 10; SheetTotal: 15
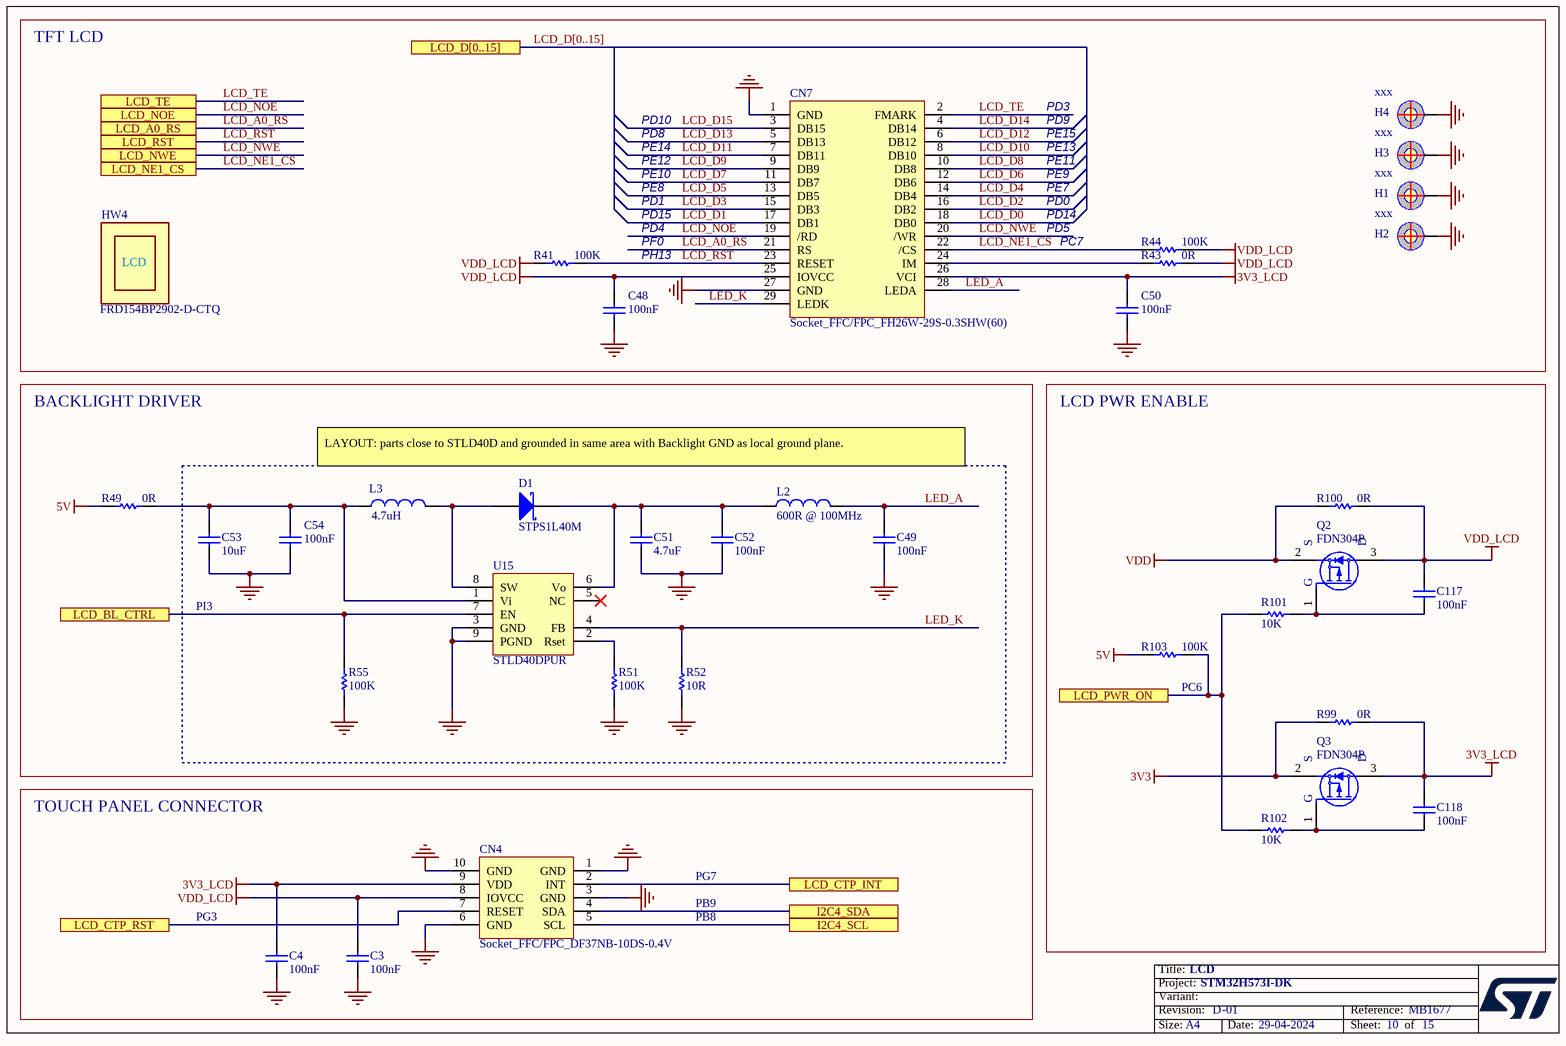
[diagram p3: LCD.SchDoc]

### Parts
C3  value 100nF  [C0402]  (hidden comment: Capacitor)
C4  value 100nF  [C0402]  (hidden comment: Capacitor)
C48  value 100nF  [C0402]  (hidden comment: Capacitor)
C49  value 100nF  [C0603]  (hidden comment: Capacitor)
C50  value 100nF  [C0402]  (hidden comment: Capacitor)
C51  value 4.7uF  [C1206_H1P25]  (hidden comment: Capacitor)
C52  value 100nF  [C0603]  (hidden comment: Capacitor)
C53  value 10uF  [C0603]  (hidden comment: Capacitor)
C54  value 100nF  [C0402]  (hidden comment: Capacitor)
C117  value 100nF  [C0402]  (hidden comment: Capacitor)
C118  value 100nF  [C0402]  (hidden comment: Capacitor)
CN4  value Socket_FFC/FPC_DF37NB-10DS-0.4V  [CON_HRS_DF37NB-10DS-04V]  (hidden comment: DF37NB-10DS-0.4V)
CN7  value Socket_FFC/FPC_FH26W-29S-0.3SHW(60)  [CON_HRS_FH26-29S-03SHW]  (hidden comment: FH26-29S-0.3SHW)
D1  STPS1L40M  [DIO_DO216-AA]
H1  value xxx  [PTH_M1261-3005-N_3P5X6_M3_H14]  (hidden comment: POSITION HOLE)  (no BOM)
H2  value xxx  [PTH_M1261-3005-N_3P5X6_M3_H14]  (hidden comment: POSITION HOLE)  (no BOM)
H3  value xxx  [PTH_M1261-3005-N_3P5X6_M3_H14]  (hidden comment: POSITION HOLE)  (no BOM)
H4  value xxx  [PTH_M1261-3005-N_3P5X6_M3_H14]  (hidden comment: POSITION HOLE)  (no BOM)
HW4  value FRD154BP2902-D-CTQ  [LCD_DRAWING_FRIDA_FRD154BP2902-D-CTQ]  (hidden comment: LCD_MODULE)  (mechanical)
L2  value 600R @ 100MHz  [L0603]  (hidden comment: BEAD)
L3  value 4.7uH  [L1210_LQH]  (hidden comment: Inductor)
Q2  value FDN304P  [MOS_SOT23]  (hidden comment: MOSFET_FDN304P)
Q3  value FDN304P  [MOS_SOT23]  (hidden comment: MOSFET_FDN304P)
R41  value 100K  [R0402]  (hidden comment: Resistor)
R43  value 0R  [R0402]  (hidden comment: Resistor)
R44  value 100K  [R0402]  (hidden comment: Resistor)
R49  value 0R  [R0402]  (hidden comment: Resistor)
R51  value 100K  [R0402]  (hidden comment: Resistor)
R52  value 10R  [R0402]  (hidden comment: Resistor)
R55  value 100K  [R0402]  (hidden comment: Resistor)
R99  value 0R  [R0402]  (hidden comment: Resistor)
R100  value 0R  [R0402]  (hidden comment: Resistor)
R101  value 10K  [R0402]  (hidden comment: Resistor)
R102  value 10K  [R0402]  (hidden comment: Resistor)
R103  value 100K  [R0402]  (hidden comment: Resistor)
U15  STLD40DPUR  [ICC_QFN8-EPAD_3X3_P065]

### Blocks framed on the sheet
TFT LCD: C48 C50 CN7 H1-H4 HW4 R41 R43 R44
BACKLIGHT DRIVER: R49
LCD PWR ENABLE: C117 C118 Q2 Q3 R99-R103
PI3: C49 C51-C54 D1 L2 L3 R51 R52 R55 U15
TOUCH PANEL CONNECTOR: C3 C4 CN4

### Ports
I2C4_SCL, I2C4_SDA, LCD_A0_RS, LCD_BL_CTRL, LCD_CTP_INT, LCD_CTP_RST, LCD_D[0..15], LCD_NE1_CS, LCD_NOE, LCD_NWE, LCD_PWR_ON, LCD_RST, LCD_TE

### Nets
3V3: Q3.2(S) R99.1
3V3_LCD: C4.2 C50.1 C118.2 CN4.9(VDD) CN7.26(VCI) Q3.3(D) R99.2
5V: R49.1 R103.1
GND: C3.1 C4.1 C48.2 C49.1 C50.2 C51.1 C52.1 C53.1 C54.2 CN4.1(GND) CN4.3(GND) CN4.6(GND) CN4.10(GND) CN7.1(GND) CN7.27(GND) H1.1 H2.1 H3.1 H4.1 R51.1 R52.1 R55.1 U15.3(GND) U15.9(PGND)
VDD: Q2.2(S) R100.1
VDD_LCD: C3.2 C48.1 C117.2 CN4.8(IOVCC) CN7.25(IOVCC) Q2.3(D) R41.1 R43.2 R44.2 R100.2
I2C4_SCL: CN4.5(SCL) ; port I2C4_SCL
I2C4_SDA: CN4.4(SDA) ; port I2C4_SDA
LCD_A0_RS: CN7.21(RS) ; port LCD_A0_RS
LCD_BL_CTRL: R55.2 U15.7(EN) ; port LCD_BL_CTRL
LCD_CTP_INT: CN4.2(INT) ; port LCD_CTP_INT
LCD_CTP_RST: CN4.7(RESET) ; port LCD_CTP_RST
LCD_D0: CN7.18(DB0)
LCD_D1: CN7.17(DB1)
LCD_D2: CN7.16(DB2)
LCD_D3: CN7.15(DB3)
LCD_D4: CN7.14(DB4)
LCD_D5: CN7.13(DB5)
LCD_D6: CN7.12(DB6)
LCD_D7: CN7.11(DB7)
LCD_D8: CN7.10(DB8)
LCD_D9: CN7.9(DB9)
LCD_D10: CN7.8(DB10)
LCD_D11: CN7.7(DB11)
LCD_D12: CN7.6(DB12)
LCD_D13: CN7.5(DB13)
LCD_D14: CN7.4(DB14)
LCD_D15: CN7.3(DB15)
LCD_NE1_CS: CN7.22(/CS) R44.1 ; port LCD_NE1_CS
LCD_NOE: CN7.19(/RD) ; port LCD_NOE
LCD_NWE: CN7.20(/WR) ; port LCD_NWE
LCD_PWR_ON: R101.1 R102.1 R103.2 ; port LCD_PWR_ON
LCD_RST: CN7.23(RESET) R41.2 ; port LCD_RST
LCD_TE: CN7.2(FMARK) ; port LCD_TE
LED_A: C49.2 CN7.28(LEDA) L2.2
LED_K: CN7.29(LEDK) R52.2 U15.4(FB)
NetC51_2: C51.2 C52.2 D1.2(K) L2.1 U15.6(Vo)
NetC53_2: C53.2 C54.1 L3.1 R49.2 U15.1(Vi)
NetC117_1: C117.1 Q2.1(G) R101.2
NetC118_1: C118.1 Q3.1(G) R102.2
NetCN7_24: CN7.24(IM) R43.1
NetD1_1: D1.1(A) L3.2 U15.8(SW)
NetR51_2: R51.2 U15.2(Rset)

Not connected (* = marked no-connect by the designer): U15 5(NC)*

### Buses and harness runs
bus LCD_D[0..15] = port LCD_D[0..15]

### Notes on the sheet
- PD3
- PD10
- PD8
- PE14
- PE12
- PE10
- PD9
- PE15
- PE13
- PE11
- PE9
- PE8
- PD1
- PD15
- PD4
- PF0
- PE7
- PD0
- PD14
- PD5
- PC7
- PH13
- LAYOUT: parts close to STLD40D and grounded in same area with Backlight GND as local ground plane.
- (near R103) PC6
- PG3
- PB9
- PB8
- PG7

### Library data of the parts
C3 C4 C48 C50 C54 C117 C118 = MCD-00006: Capacitor, MLCC, 100nF, 16V, X7R, +/-10%, 0402, T=0.5mm; Manufacturer_Part_Number: CC0402KRX7R7BB104; Manufacturer: YAGEO; Part_Preference: Recommended; Partial_Alternate_Internal_Part_Number: MCD-03299; Component_Country_Of_Origin: China; ID: 2474; Order_Code_RS: 9402047; ShowFields: YES
C49 C52 = MCD-01099: Capacitor,100nF,50V,X7R,10%,0603; Manufacturer_Part_Number: CC0603KRX7R9BB104; Manufacturer: YAGEO; BMS_Part_Number: 9142278; Part_Preference: Recommended; Provided_By: SUBCO; Component_Country_Of_Origin: China; ID: 3397; Order_Code_RS: 669-8767; ShowFields: YES
C51 = MCD-00013: Capacitor, MLCC, 4.7uF, 50V, X7R, 10%, 1206, T=1,27mm; Manufacturer_Part_Number: 12065C475KAT2A; Manufacturer: AVX; Part_Preference: Recommended; ECCN_US: EAR99; ECCN_EU: NEC; Provided_By: SUBCO; Component_Country_Of_Origin: China, Malaysia; ID: 2466; Order_Code_RS: 1908177; ShowFields: YES
C53 = MCD-00099: Capacitor, MLCC, 10uF, 10V, X5R, +/-10%, 0603, T=0.8mm; Manufacturer_Part_Number: GRM188R61A106KE69D; Manufacturer: MURATA; Part_Preference: Recommended; Partial_Alternate_Internal_Part_Number: MCD-03152; Component_Country_Of_Origin: Japan°°; ID: 2770; Order_Code_RS: 2494233; ShowFields: YES
CN4 = MCD-00021: Socket FCC/FPC, 5x2, 0.4mm, VR, SMT, 0.98mm, Frida touch panel; Part_Type: Connector; Manufacturer_Part_Number: DF37NB-10DS-0.4V (5x); Manufacturer: HIROSE; Part_Preference: Recommended; Provided_By: SUBCO; Component_Country_Of_Origin: Japan; ID: 2499; ShowFields: YES
CN7 = MCD-01798: Socket FCC/FPC, 29pins, 0.6mm, SMT, for FRIDA LCD (replacement of obsolete component MCD-00020 FH26-29S-0.3SHW); Part_Type: Connector; Manufacturer_Part_Number: FH26W-29S-0.3SHW(60); Manufacturer: HIROSE; Part_Preference: Recommended; Provided_By: SUBCO; Component_Country_Of_Origin: Japan; ID: 3898; ShowFields: YES
D1 = MCD-00033: Low Drop power Schottky rectifier(1A, 40V, 0.4V); Part_Type: Diode; Manufacturer: STMICROELECTRONICS; BMS_Part_Number: 9151085; Manufacturer_HQ_COO: EU; Part_Preference: Recommended; ECCN_US: EAR99; ECCN_EU: NEC; Provided_By: SUBCO with ST control; Component_Country_Of_Origin: China; ID: 2485; Order_Code_RS: 189-4505; ShowFields: YES
H1-H4 = MCD-00035: POSITION HOLE C6D3R5; Part_Type: Misc; Part_Preference: Recommended; Component_Country_Of_Origin: Unknown; ID: 2482; ShowFields: YES
HW4 = MCD-01797: TFT LCD 1.54inch 240RGB x 240 pixels + CTP; BMS_Part_Number: 8001061; Part_Type: Display; Part_Preference: Recommended; Manufacturer: SHENZEN FRIDA LCD; Component_Country_Of_Origin: China; ID: 3897; ShowFields: YES
L2 = MCD-00047: SMD Chip ferrite bead, 600R@100MHz +/-25%, 350mA, 500mohm DC, 0603, T=0.8mm; Part_Type: Inductor; Manufacturer_Part_Number: FCM1608KF-601T03; Manufacturer: TAI-TECH; Part_Preference: Recommended; Partial_Alternate_Internal_Part_Number: MCD-02959; Provided_By: SUBCO; Component_Country_Of_Origin: Unknown; ID: 2546; ShowFields: YES
L3 = MCD-00048: FIXED IND 4.7UH 1A 180 MOHM 30% SMD; Manufacturer_Part_Number: LQH32PN4R7NN0L; Manufacturer: MURATA; Part_Preference: Recommended; Provided_By: SUBCO; Component_Country_Of_Origin: Japan°°; ID: 2544; Order_Code_RS: 2470296; ShowFields: YES
Q2 Q3 = MCD-01494: MOSFET, P-Channel , Vds: -20V, Id: -2.4A, Vgs(th): -1.5V, Vgs(max): +/-8V, Rdson:100mohm@Vgs=-1.8V; Part_Type: IC; Manufacturer: ON SEMICONDUCTOR; Alternate_Manufacturer_Part_Number: FDN304PZ; Part_Preference: Recommended; ECCN_US: EAR99; ECCN_EU: NEC; Provided_By: SUBCO; Component_Country_Of_Origin: Philippines°°; ID: 3594; ShowFields: YES
R41 R44 R51 R55 R103 = MCD-00059: Resistor,100K,0402,1%,1/16W; Manufacturer_Part_Number: RC0402FR-07100KL; Manufacturer: YAGEO; Alternate_Manufacturer_Part_Number: RT0402FRE07100KL; Part_Preference: Recommended; Partial_Alternate_Internal_Part_Number: MCD-03301; ECCN_US: EAR99; ECCN_EU: NEC; Provided_By: SUBCO; Component_Country_Of_Origin: China; ID: 2533; Order_Code_RS: 2421891; ShowFields: YES
R43 R49 R99 R100 = MCD-00052: Resistor,0R,0402,5%,1/16W; Manufacturer_Part_Number: RC0402JR-070RL; Manufacturer: YAGEO; Part_Preference: Recommended; ECCN_US: EAR99; ECCN_EU: NEC; Provided_By: SUBCO; Component_Country_Of_Origin: China; ID: 2540; Order_Code_RS: 9232516RL; ShowFields: YES
R52 = MCD-00358: Resistor,10R,0402,1%,1/16W; Part_Preference: Recommended; Manufacturer: YAGEO; Manufacturer_Part_Number: RC0402FR-0710RL; Order_Code_RS: 618-5848; Component_Country_Of_Origin: China; ID: 2919; ShowFields: YES
R101 R102 = MCD-00053: Resistor,10K,0402,1%,1/16W; Manufacturer_Part_Number: RC0402FR-0710KL; Manufacturer: YAGEO; BMS_Part_Number: 9131590; Part_Preference: Recommended; ECCN_US: EAR99; ECCN_EU: NEC; Provided_By: SUBCO; Component_Country_Of_Origin: China; ID: 2539; Order_Code_RS: 9239359; ShowFields: YES
U15 = MCD-00082: White LED power supply for large display backlight, QFN8; Part_Type: IC; Manufacturer: STMICROELECTRONICS; BMS_Part_Number: 9176009; Manufacturer_HQ_COO: EU; Part_Preference: Recommended; ECCN_US: EAR99; ECCN_EU: NEC; Provided_By: SUBCO with ST control; Component_Country_Of_Origin: Malaysia; ID: 2510; Order_Code_RS: 188-9216; ShowFields: YES

## Sheet Peripherals.SchDoc: Peripherals
size A4; Date: Not used; ApprovedBy: Not used; CheckedBy: Not used; Author: Not used; CompanyName: STMicroelectronics; DrawnBy: Not used; Engineer: Not used; Organization: Not used; Address1: Not used; Address2: Not used; Address3: Not used; Address4: Not used; DocumentNumber: 12; Revision: Not used; SheetNumber: 12; SheetTotal: 15
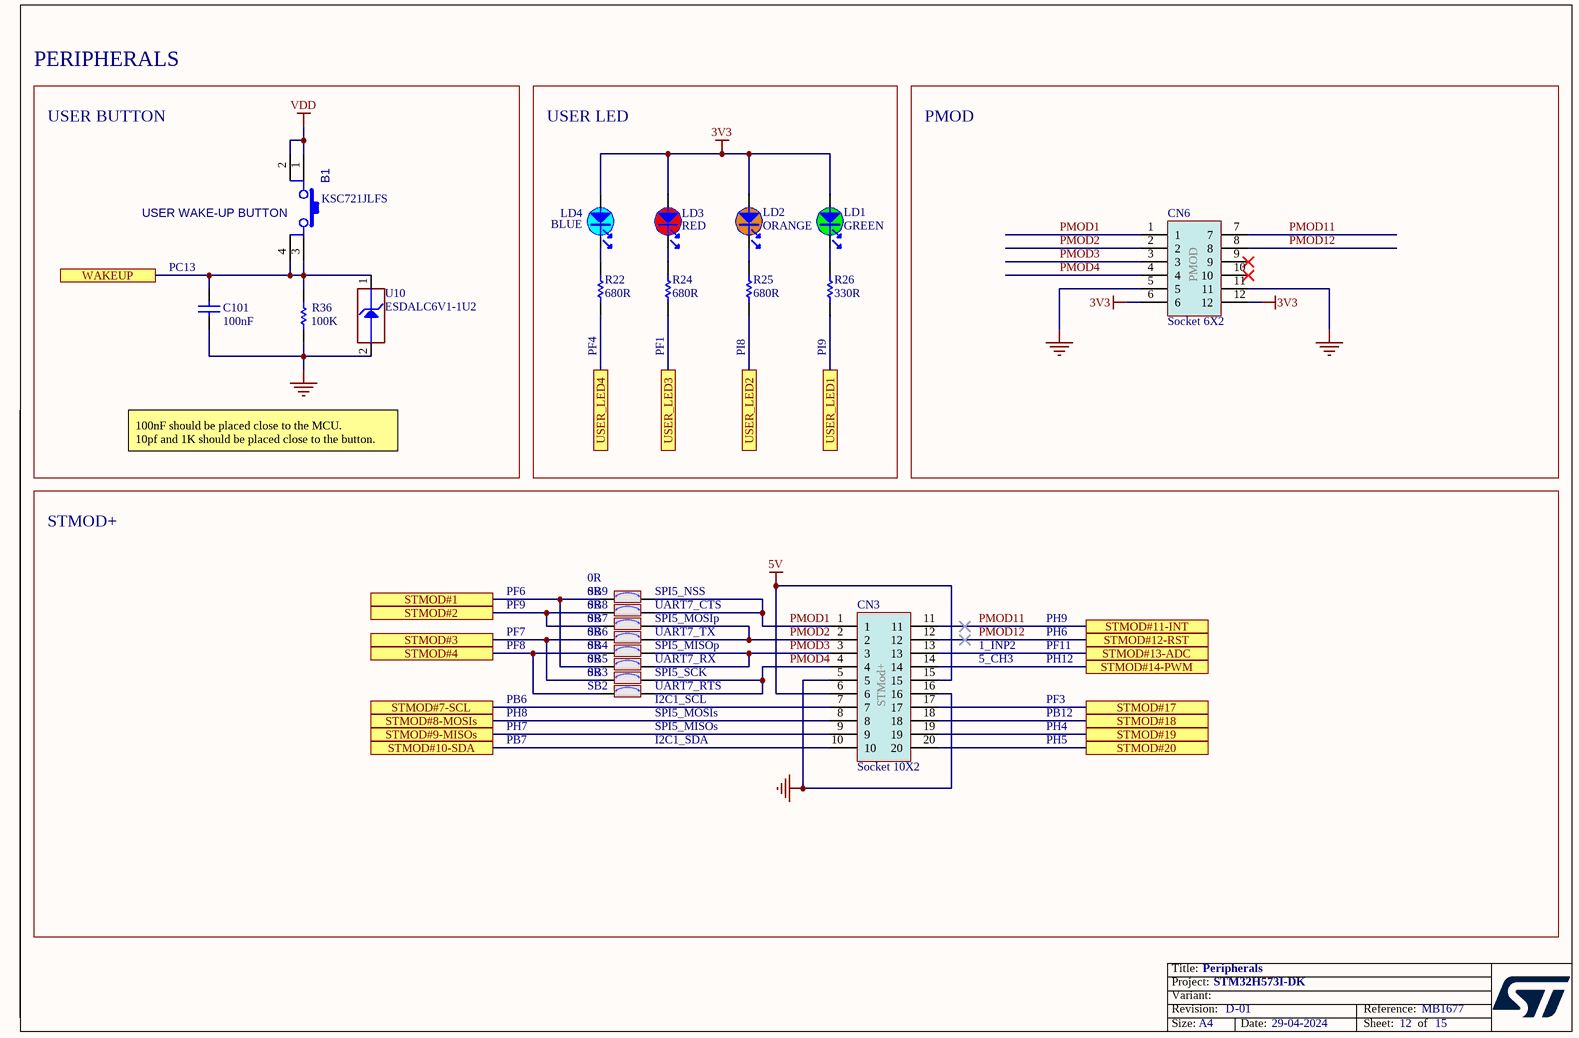
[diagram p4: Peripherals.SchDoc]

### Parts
B1  value KSC721JLFS  [SWI_C&K_KSC721JLFS_BLUE]  (hidden comment: SW_BLUE_KSC721JLFS)
C101  value 100nF  [C0402]  (hidden comment: Capacitor)
CN3  value Socket 10X2  [CON_SAMTEC_SQT-110-01-F-D-RA__STMOD+]  (hidden comment: Socket 10X2 STMod+)
CN6  value Socket 6X2  [CON_SAMTEC_SSW-106-02-F-D-RA__PMOD]  (hidden comment: Socket 6X2 PMOD)
LD1  value GREEN  [LED_0603_OSRAM_LG-Q396-PS-35_GREEN_1A2K_H0P4]  (hidden comment: LED_green)
LD2  value ORANGE  [LED_0603_OSRAM_LO-Q976-PS-25_ORANGE_1A2K_H0P8]  (hidden comment: LED_orange)
LD3  value RED  [LED_0603_VISHAY_VLMS1300-GS08_RED_1A2K_H0P8]  (hidden comment: LED_red)
LD4  value BLUE  [LED_0603_OSRAM_LB-Q39G-L2OO-35-1_BLUE_1A2K_H0P4]  (hidden comment: LED_blue)
R22  value 680R  [R0402]  (hidden comment: Resistor)
R24  value 680R  [R0402]  (hidden comment: Resistor)
R25  value 680R  [R0402]  (hidden comment: Resistor)
R26  value 330R  [R0402]  (hidden comment: Resistor)
R36  value 100K  [R0402]  (hidden comment: Resistor)
SB2  value 0R  [SOLDER-BRIDGE_R0603-0R]  (hidden comment: SB_ON)
SB3  value 0R  [SOLDER-BRIDGE_R0603-0R]  (hidden comment: SB_ON)
SB4  value 0R  [SOLDER-BRIDGE_R0603-0R]  (hidden comment: SB_ON)
SB5  value 0R  [SOLDER-BRIDGE_R0603-0R]  (hidden comment: SB_ON)
SB6  value 0R  [SOLDER-BRIDGE_R0603-0R]  (hidden comment: SB_ON)
SB7  value 0R  [SOLDER-BRIDGE_R0603-0R]  (hidden comment: SB_ON)
SB8  value 0R  [SOLDER-BRIDGE_R0603-0R]  (hidden comment: SB_ON)
SB9  value 0R  [SOLDER-BRIDGE_R0603-0R]  (hidden comment: SB_ON)
U10  value ESDALC6V1-1U2  [ESD_ST0201]  (hidden comment: ESD-TRANSIL)

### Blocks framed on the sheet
PERIPHERALS: B1 C101 R36 U10
USER LED: LD1-LD4 R22 R24-R26
PMOD: CN6
STMOD+: CN3 SB2-SB9

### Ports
STMOD#1, STMOD#2, STMOD#3, STMOD#4, STMOD#7-SCL, STMOD#8-MOSIs, STMOD#9-MISOs, STMOD#10-SDA, STMOD#11-INT, STMOD#12-RST, STMOD#13-ADC, STMOD#14-PWM, STMOD#17, STMOD#18, STMOD#19, STMOD#20, USER_LED1, USER_LED2, USER_LED3, USER_LED4, WAKEUP

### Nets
3V3: CN6.6 CN6.12 LD1.1 LD2.1 LD3.1 LD4.1
5V: CN3.6 CN3.15
GND: C101.1 CN3.5 CN3.16 CN6.5 CN6.11 R36.1 U10.2(GND)
VDD: B1.1 B1.2
PMOD1: CN3.1 CN6.1 SB8.2 SB9.2
PMOD2: CN3.2 CN6.2 SB6.2 SB7.2
PMOD3: CN3.3 CN6.3 SB4.2 SB5.2
PMOD4: CN3.4 CN6.4 SB2.2 SB3.2
PMOD11: CN3.11 CN6.7 ; port STMOD#11-INT
PMOD12: CN3.12 CN6.8 ; port STMOD#12-RST
STMOD#1: SB5.1 SB9.1 ; port STMOD#1
STMOD#2: SB7.1 SB8.1 ; port STMOD#2
STMOD#3: SB3.1 SB6.1 ; port STMOD#3
STMOD#4: SB2.1 SB4.1 ; port STMOD#4
STMOD#7-SCL: CN3.7 ; port STMOD#7-SCL
STMOD#8-MOSIs: CN3.8 ; port STMOD#8-MOSIs
STMOD#9-MISOs: CN3.9 ; port STMOD#9-MISOs
STMOD#10-SDA: CN3.10 ; port STMOD#10-SDA
STMOD#13-ADC: CN3.13 ; port STMOD#13-ADC
STMOD#14-PWM: CN3.14 ; port STMOD#14-PWM
STMOD#17: CN3.17 ; port STMOD#17
STMOD#18: CN3.18 ; port STMOD#18
STMOD#19: CN3.19 ; port STMOD#19
STMOD#20: CN3.20 ; port STMOD#20
USER_LED1: R26.1 ; port USER_LED1
USER_LED2: R25.1 ; port USER_LED2
USER_LED3: R24.1 ; port USER_LED3
USER_LED4: R22.1 ; port USER_LED4
WAKEUP: B1.3 B1.4 C101.2 R36.2 U10.1(IO1) ; port WAKEUP
NetLD1_2: LD1.2 R26.2
NetLD2_2: LD2.2 R25.2
NetLD3_2: LD3.2 R24.2
NetLD4_2: LD4.2 R22.2

Not connected (* = marked no-connect by the designer): CN6 9* 10*

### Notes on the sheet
- USER BUTTON
- (near B1) USER WAKE-UP BUTTON
- (near C101) PC13
- (near R22) PF4
- (near R24) PF1
- (near R25) PI8
- (near R26) PI9
- 100nF should be placed close to the MCU.
  10pf and 1K should be placed close to the button.
- PF6
- PF7
- PF8
- PF9
- SPI5_NSS
- UART7_CTS
- SPI5_MOSIp
- UART7_TX
- SPI5_MISOp
- 1_INP2
- PF11
- PH9
- PH6
- PB6
- PH8
- UART7_RX
- SPI5_SCK
- UART7_RTS
- SPI5_MOSIs
- I2C1_SCL
- 5_CH3
- PH12
- PF3
- PB12
- PB7
- PH7
- SPI5_MISOs
- I2C1_SDA
- PH5
- PH4

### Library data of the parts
B1 = MCD-01800: Switch HW BLUE High4.3mm 2.25 Newtons, BEND type; Part_Type: Misc; Part_Preference: Recommended; Manufacturer: C&K; Partial_Alternate_Internal_Part_Number: MCD-03151; Component_Country_Of_Origin: France; ShowFields: YES; ID: 3900
C101 = MCD-00006: as C3 on sheet LCD
CN3 = MCD-00309: Socket 10x2, 2.00mm, RA, TH, Height 6.35mm/2.29mm; Part_Preference: Recommended; Part_Type: Connector; Manufacturer: SAMTEC; Manufacturer_Part_Number: SQT-110-01-F-D-RA; Alternate_Manufacturer: JIUBABA;CONNECT; Alternate_Manufacturer_Part_Number: FH200020C-12300;CNT-F200-2*10-GD-635/2.3; Partial_Alternate_Internal_Part_Number: MCD-03873; Component_Country_Of_Origin: China, Costa Rica, Malaysia, USA, Vietnam; ID: 2557; Order_Code_RS: 180-1541; ShowFields: YES
CN6 = MCD-00308: Socket, 6x2, 2.54mm, TH, RA, Height 8.51mm/7.62mm; Part_Type: Connector; Manufacturer_Part_Number: SSW-106-02-F-D-RA; Manufacturer: SAMTEC; Part_Preference: Recommended; Provided_By: SUBCO; Component_Country_Of_Origin: China, Costa Rica, Malaysia, USA, Vietnam; ID: 2562; Order_Code_RS: 207-9142; ShowFields: YES
LD1 = MCD-00588: LED Green, 0603 SMD, Forward Voltage Typ=2V, Max=2.5V; Part_Preference: Recommended; Part_Type: Display; Manufacturer: OSRAM OPTO SEMICONDUCTORS; Manufacturer_Part_Number: LG Q396-PS-35; Alternate_Manufacturer: VISHAY SEMICONDUCTOR OPTO DIVISION; Alternate_Manufacturer_Part_Number: VLMTG1300-GS08; Partial_Alternate_Internal_Part_Number: MCD-02400, MCD-03155; Component_Country_Of_Origin: Unknown; ID: 3155; ShowFields: YES
LD2 = MCD-00590: LED Orange, 0603 SMD, Forward Voltage Min=1.6V, Max=2.4V; Part_Preference: Recommended; Part_Type: Display; Manufacturer: OSRAM OPTO SEMICONDUCTORS; Manufacturer_Part_Number: LO Q976-PS-25; Alternate_Manufacturer: VISHAY SEMICONDUCTOR OPTO DIVISION; Alternate_Manufacturer_Part_Number: VLMO1300-GS08; Component_Country_Of_Origin: Unknown; ID: 3156; ShowFields: YES
LD3 = MCD-00587: LED Red, 0603 SMD, 2V Forward Voltage; Manufacturer_Part_Number: VLMS1300-GS08; Manufacturer: VISHAY; Alternate_Manufacturer_Part_Number: LS Q976-NR-1; Alternate_Manufacturer: OSRAM OPTO SEMICONDUCTORS; Part_Type: Display; Full_Alternate_Internal_Part_Number: MCD-02401; Part_Preference: Recommended; Provided_By: SUBCO; Component_Country_Of_Origin: China; ID: 3154; ShowFields: YES
LD4 = MCD-00585: LED Blue, 0603 SMD, Forward Voltage Min=2,8V, Max=3,8V; Manufacturer_Part_Number: LB Q39G-L2OO-35-1; Manufacturer: OSRAM OPTO SEMICONDUCTORS; Part_Type: Display; Alternate_Manufacturer_Part_Number: 19-217-BHC-ZL1M2RY-3T-V4; Alternate_Manufacturer: EVERLIGHT; Full_Alternate_Internal_Part_Number: MCD-02398; Part_Preference: Recommended; Order_Code_RS: 9148643; Provided_By: SUBCO; Component_Country_Of_Origin: Unknown; ID: 3159; ShowFields: YES
R22 R24 R25 = MCD-00507: Resistor,680R,0402,1%,1/16W; Part_Preference: Recommended; Manufacturer: YAGEO; Manufacturer_Part_Number: RC0402FR-07680RL; Component_Country_Of_Origin: China; ID: 3238; ShowFields: YES
R26 = MCD-00062: Resistor,330R,0402,1%,1/16W; Manufacturer_Part_Number: RC0402FR-07330RL; Manufacturer: YAGEO; Part_Preference: Recommended; Provided_By: SUBCO; Component_Country_Of_Origin: China; ID: 2529; Order_Code_RS: 9239170; ShowFields: YES
R36 = MCD-00059: Resistor,100K,0402,1%,1/16W; Manufacturer_Part_Number: RC0402FR-07100KL; Manufacturer: YAGEO; Alternate_Manufacturer_Part_Number: RT0402FRE07100KL; Part_Preference: Recommended; Partial_Alternate_Internal_Part_Number: MCD-03301; Provided_By: SUBCO; Component_Country_Of_Origin: China; ID: 2533; Order_Code_RS: 2421891; ShowFields: YES
SB2-SB9 = MCD-00071: as SB1 on sheet Audio_Codec
U10 = MCD-00170: ESD protection 6V1; Part_Type: Diode; Manufacturer: STMICROELECTRONICS; BMS_Part_Number: 9151132; Manufacturer_HQ_COO: EU; Part_Preference: Recommended; Provided_By: SUBCO with ST control; Component_Country_Of_Origin: China; ID: 2696; Order_Code_RS: 795-8404; ShowFields: YES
